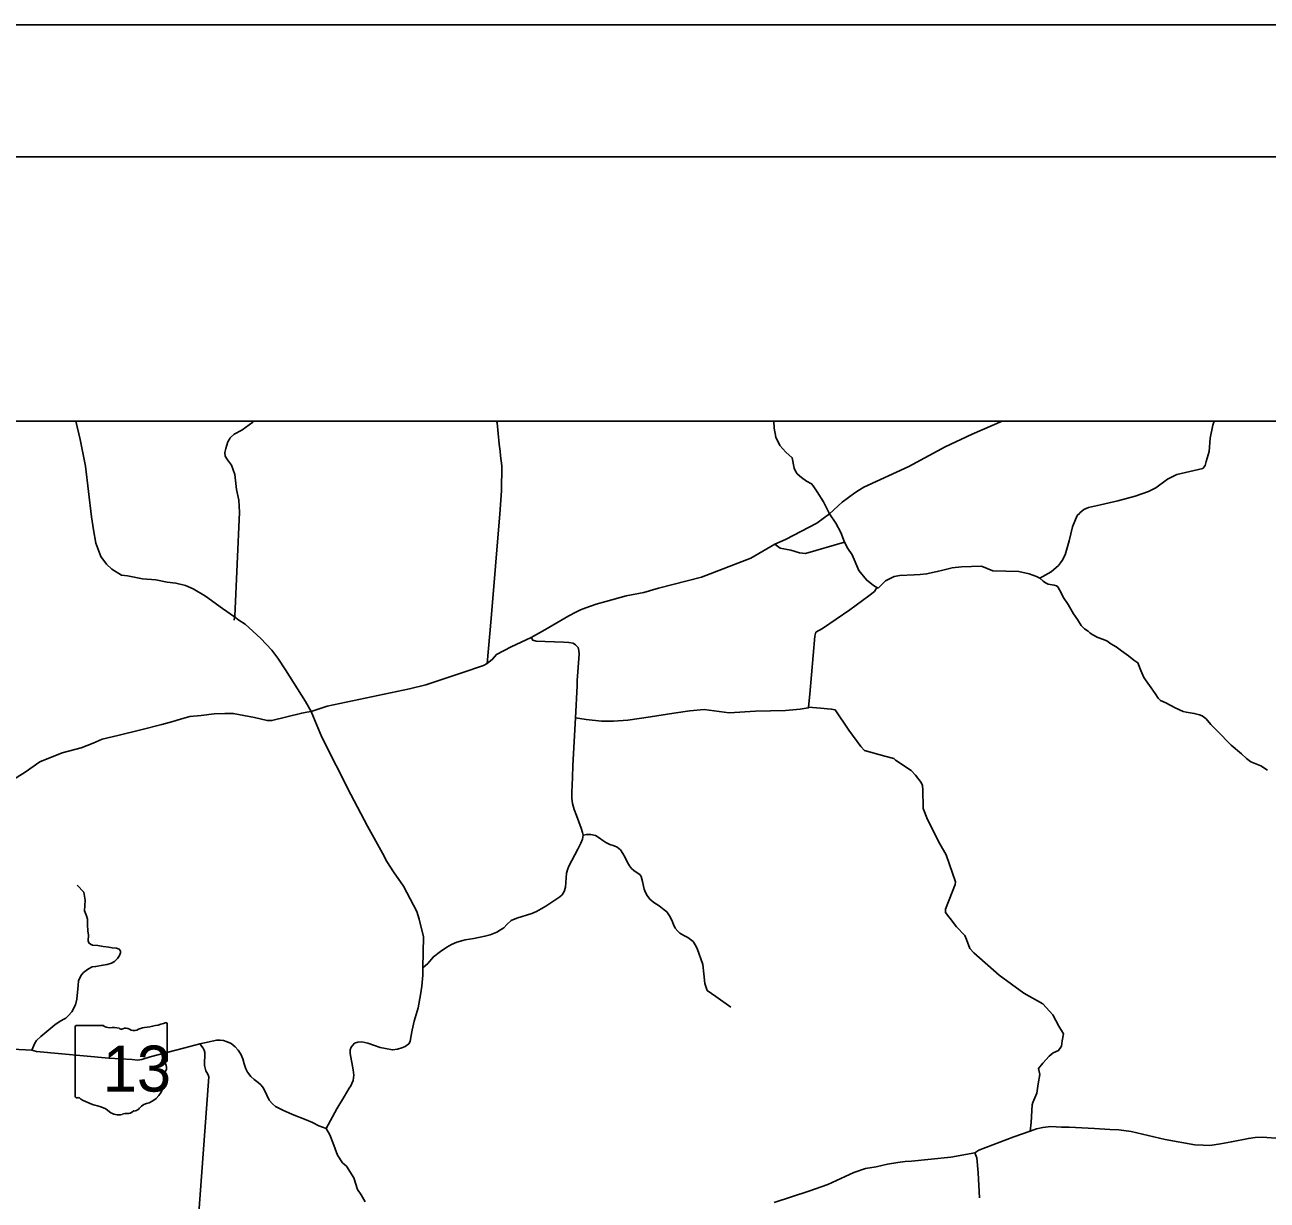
# Model space of a CAD drawing. Extents: x 2025369 to 2161369, y 549489 to 637489.
# Drawn here: x 2056140 to 2074950, y 619698 to 637489 of the extents above; entities that cross this region are included whole.
import ezdxf

# ---------------------------------------------------------------- set-up
doc = ezdxf.new("R2010")
doc.units = 0
for name, color, linetype in [('GM_X_County_Road', 7, 'Continuous'), ('GM_X_State_Route', 7, 'Continuous'), ('GM_X_State_Shield', 7, 'Continuous'), ('GM_X_Township_Road', 7, 'Continuous'), ('SH_Border', 7, 'Continuous'), ('SH_Cut_Line', 7, 'Continuous'), ('SH_Text', 7, 'Continuous')]:
    doc.layers.add(name, color=color, linetype=linetype)

msp = doc.modelspace()

# ---------------------------------------------------------------- linework, layer by layer
at = {"layer": 'GM_X_County_Road'}
for points in [[(2060474, 627097), (2060388, 627244), (2060085, 627725), (2059968, 627901), (2059882, 628022), (2059715, 628201), (2059590, 628313), (2059475, 628416), (2059381, 628478), (2059316, 628529), (2059135, 628654), (2058875, 628843), (2058686, 628953), (2058570, 629004), (2058427, 629039), (2058297, 629053), (2058123, 629087), (2057922, 629105), (2057692, 629151), (2057603, 629159), (2057457, 629250), (2057374, 629323), (2057292, 629442), (2057217, 629642), (2057181, 629846), (2057148, 630040), (2057058, 630808), (2056976, 631214), (2056910, 631489)], [(2068778, 630450), (2068845, 630491), (2069524, 630805), (2070075, 631103), (2070481, 631295), (2070939, 631489)], [(2072114, 630099), (2072116, 630101), (2072172, 630152), (2072243, 630184), (2072429, 630225), (2072690, 630285), (2072950, 630355), (2073152, 630423), (2073266, 630480), (2073439, 630612), (2073584, 630685), (2073976, 630774), (2074009, 630817), (2074026, 630881), (2074073, 631030), (2074087, 631235), (2074127, 631430), (2074150, 631489)], [(2055926, 626042), (2056143, 626179), (2056367, 626333), (2056707, 626468), (2056991, 626543), (2057173, 626618), (2057309, 626676), (2057547, 626731), (2057896, 626816), (2058216, 626899), (2058382, 626944), (2058496, 626978), (2058640, 627017), (2058812, 627035), (2059006, 627058), (2059166, 627065), (2059233, 627065), (2059295, 627065), (2059617, 627004), (2059808, 626957), (2059882, 626957), (2060332, 627070), (2060411, 627087), (2060474, 627097), (2060718, 627178), (2061962, 627440), (2062213, 627498), (2062758, 627679), (2063085, 627790), (2063138, 627821), (2063221, 627887), (2063279, 627959), (2063505, 628074), (2063806, 628217), (2064013, 628331), (2064375, 628541), (2064492, 628605), (2064555, 628635), (2064634, 628666), (2064791, 628718), (2064938, 628762), (2065245, 628845), (2065511, 628898), (2065733, 628960), (2066385, 629131), (2067131, 629415), (2067496, 629629), (2067656, 629701), (2068130, 629945), (2068322, 630088), (2068516, 630263), (2068708, 630407), (2068778, 630450)], [(2068322, 630088), (2068417, 629946), (2068496, 629803), (2068549, 629659), (2068602, 629562), (2068666, 629467), (2068767, 629231), (2068883, 629088), (2068992, 629002), (2069042, 628974), (2069062, 628963), (2069173, 629072), (2069300, 629138), (2069386, 629156), (2069603, 629162), (2069696, 629170)], [(2069696, 629170), (2069794, 629178), (2069955, 629213), (2070039, 629234), (2070179, 629268), (2070320, 629285), (2070623, 629296), (2070794, 629223), (2071189, 629212), (2071345, 629179), (2071459, 629137), (2071510, 629113), (2071679, 629210), (2071790, 629304), (2071821, 629344), (2071848, 629380), (2071893, 629465), (2071952, 629681), (2072005, 629889), (2072075, 630060), (2072114, 630099)], [(2067496, 629629), (2067575, 629569), (2067738, 629537), (2067867, 629498), (2067962, 629486), (2068549, 629659)], [(2064501, 627486), (2064505, 627564), (2064532, 627962), (2064526, 628019), (2064517, 628063), (2064479, 628105), (2064442, 628128), (2064376, 628139), (2064297, 628143), (2063883, 628162), (2063832, 628173), (2063806, 628217)], [(2064430, 626096), (2064439, 626277), (2064478, 626998), (2064501, 627486)], [(2062770, 623629), (2062806, 623639), (2062940, 623659), (2063107, 623692), (2063185, 623714), (2063288, 623754), (2063344, 623788), (2063393, 623818), (2063436, 623873), (2063505, 623933), (2063590, 623968), (2063814, 624035), (2063888, 624067), (2064030, 624150), (2064240, 624287), (2064276, 624321), (2064307, 624370), (2064325, 624437), (2064335, 624579), (2064342, 624650), (2064360, 624713), (2064378, 624754), (2064513, 625012), (2064560, 625103), (2064584, 625164), (2064596, 625221), (2064585, 625262), (2064562, 625331), (2064492, 625523), (2064459, 625609), (2064431, 625704), (2064422, 625779), (2064420, 625876), (2064430, 626096)], [(2057586, 623467), (2057585, 623476), (2057569, 623499), (2057529, 623511), (2057464, 623515), (2057410, 623528), (2057326, 623540), (2057247, 623551), (2057163, 623559), (2057134, 623572), (2057109, 623593), (2057100, 623624), (2057102, 623710), (2057092, 623777), (2057090, 623865), (2057088, 623950), (2057075, 624003), (2057042, 624078), (2057054, 624237), (2057033, 624360), (2056933, 624467)], [(2061092, 621465), (2061111, 621508), (2061120, 621588), (2061113, 621672), (2061065, 621916), (2061067, 621975), (2061082, 622015), (2061133, 622073), (2061182, 622090), (2061242, 622093), (2061332, 622073), (2061432, 622037), (2061521, 622011), (2061602, 621991), (2061705, 621972), (2061780, 621983), (2061849, 622004), (2061900, 622023), (2061953, 622064), (2061972, 622100), (2061986, 622166), (2062005, 622270), (2062036, 622408), (2062096, 622610), (2062133, 622807), (2062149, 622936), (2062166, 623102), (2062166, 623216), (2062240, 623279), (2062325, 623382), (2062435, 623464), (2062530, 623525), (2062599, 623567), (2062680, 623603), (2062770, 623629)], [(2056247, 621966), (2056292, 622076), (2056317, 622115), (2056381, 622175), (2056474, 622252), (2056594, 622353), (2056659, 622395), (2056720, 622430), (2056758, 622452), (2056801, 622494), (2056851, 622550), (2056907, 622655), (2056929, 622738), (2056946, 622949), (2056953, 623016), (2056970, 623062), (2056996, 623107), (2057030, 623146), (2057066, 623172), (2057102, 623198), (2057161, 623229), (2057211, 623233), (2057324, 623256), (2057385, 623266), (2057451, 623287), (2057495, 623310), (2057543, 623356), (2057575, 623402), (2057589, 623444), (2057586, 623467)], [(2060702, 620782), (2060862, 621078), (2060979, 621274), (2061053, 621392), (2061076, 621429), (2061092, 621465)]]:
    msp.add_lwpolyline(points, dxfattribs=at)
at = {"layer": 'GM_X_State_Route'}
for points in [[(2056317, 621949), (2056247, 621966), (2055166, 622026), (2054991, 622055), (2054759, 622107), (2054579, 622183), (2054430, 622277), (2054349, 622347), (2054250, 622451), (2054118, 622661), (2053956, 622954), (2053866, 623163), (2053790, 623366), (2053768, 623410), (2053723, 623428), (2053665, 623433)], [(2058791, 622063), (2058560, 622006), (2058036, 621868), (2057910, 621827), (2057853, 621819), (2057764, 621828), (2057411, 621849), (2056317, 621949)], [(2061292, 619671), (2061234, 619780), (2061179, 619860), (2061121, 620035), (2061008, 620210), (2060950, 620265), (2060873, 620381), (2060804, 620572), (2060759, 620687), (2060702, 620782), (2060645, 620802), (2060591, 620821), (2060497, 620873), (2060398, 620914), (2060191, 620992), (2060045, 621060), (2059934, 621114), (2059892, 621154), (2059839, 621209), (2059806, 621285), (2059760, 621384), (2059739, 621415), (2059714, 621442), (2059671, 621481), (2059613, 621524), (2059564, 621568), (2059513, 621633), (2059485, 621687), (2059460, 621760), (2059438, 621837), (2059410, 621909), (2059372, 621970), (2059325, 622018), (2059263, 622069), (2059203, 622095), (2059146, 622114), (2059096, 622121), (2059045, 622120), (2058791, 622063)], [(2075146, 620629), (2074879, 620652), (2074769, 620646), (2074667, 620632), (2074409, 620582), (2074243, 620548), (2074083, 620526), (2073980, 620531), (2073855, 620536), (2073407, 620616), (2072893, 620736), (2072705, 620761), (2072568, 620769), (2072337, 620784), (2071950, 620801), (2071836, 620802), (2071676, 620811), (2071553, 620796), (2071457, 620777), (2071363, 620742), (2071113, 620655), (2070585, 620454), (2070522, 620414), (2070163, 620351), (2069567, 620287), (2069470, 620284), (2069360, 620270), (2069203, 620241), (2069028, 620204), (2068870, 620175), (2068690, 620115), (2068297, 619937), (2068012, 619834), (2067487, 619663)]]:
    msp.add_lwpolyline(points, dxfattribs=at)
at = {"layer": 'GM_X_State_Shield'}
for p, q in [((2056904, 622323), (2056904, 621266)), ((2057325, 622341), (2056918, 622341)), ((2058296, 621814), (2058296, 622367)), ((2058296, 621814), (2058296, 621814))]:
    msp.add_line(p, q, dxfattribs=at)
for centre, radius, start, end in [((2056920, 622325), 16.1, 98.1301, 188.1301), ((2057422, 622464), 156, 231.6195, 271.1119), ((2057474, 621748), 562, 80.4867, 94.9883), ((2057602, 622330), 45.1, 219.7921, 297.1024), ((2057668, 622208), 93.8, 54.4667, 119.1411), ((2057789, 622376), 113, 233.8562, 294.8282), ((2057988, 622018), 297, 97.3462, 120.7689), ((2057800, 623781), 1476, 275.8445, 288.9065), ((2058281, 622369), 15.5, 351.8621, 97.738), ((2058292, 621774), 24, 107.944, 210.337), ((2058140, 621704), 144, 340.033, 23.6496), ((2058279, 621812), 16.6, 289.6038, 7.7341), ((2057883, 621513), 369, 292.3089, 8.9858), ((2058352, 621583), 105, 136.8065, 186.9296), ((2056920, 621264), 16.3, 171.9584, 258.3066), ((2056922, 621372), 124, 267.339, 280.6039), ((2056948, 621205), 44.8, 29.7484, 93.2717), ((2057513, 622154), 1066, 240.4129, 257.1985), ((2057195, 620791), 334, 47.1842, 75.836), ((2058038, 620969), 202, 94.4031, 142.5768), ((2057556, 621200), 212, 230.7004, 286.2918), ((2057678, 620835), 174, 85.6951, 111.2099), ((2057694, 621121), 113, 268.777, 315.5493), ((2057796, 621018), 31.8, 65.7517, 132.6484), ((2057782, 621164), 119, 282.8732, 323.2771)]:
    msp.add_arc(centre, radius, start, end, dxfattribs=at)
at = {"layer": 'GM_X_Township_Road'}
for points in [[(2059237, 631216), (2059250, 631240), (2059309, 631291), (2059427, 631355), (2059593, 631473), (2059609, 631489)], [(2063344, 630963), (2063335, 631035), (2063321, 631143), (2063292, 631466), (2063282, 631489)], [(2067759, 630934), (2067759, 630937), (2067664, 631023), (2067569, 631123), (2067511, 631247), (2067484, 631384), (2067483, 631489)], [(2059311, 628477), (2059316, 628529), (2059317, 628536), (2059392, 630114), (2059380, 630294), (2059347, 630456), (2059319, 630684), (2059268, 630822), (2059208, 630904), (2059173, 630960), (2059167, 631014), (2059182, 631078), (2059215, 631175), (2059237, 631216)], [(2063138, 627821), (2063201, 628502), (2063330, 630086), (2063355, 630437), (2063363, 630812), (2063344, 630963)], [(2068322, 630088), (2068233, 630267), (2068139, 630419), (2068077, 630512), (2068051, 630542), (2067974, 630584), (2067897, 630635), (2067833, 630693), (2067807, 630732), (2067787, 630777), (2067759, 630934)], [(2074953, 626208), (2074852, 626274), (2074705, 626335), (2074637, 626385), (2074560, 626456), (2074406, 626583), (2074192, 626801), (2074098, 626899), (2074025, 626985), (2073967, 627031), (2073928, 627045), (2073846, 627067), (2073725, 627084), (2073676, 627095), (2073558, 627151), (2073415, 627228), (2073333, 627263), (2073299, 627295), (2073256, 627367), (2073082, 627608), (2073036, 627718), (2072992, 627833), (2072932, 627874), (2072851, 627940), (2072747, 628015), (2072666, 628072), (2072585, 628119), (2072523, 628164), (2072459, 628192), (2072386, 628216), (2072302, 628260), (2072266, 628284), (2072239, 628310), (2072182, 628347), (2072132, 628397), (2072078, 628487), (2072019, 628575), (2071938, 628713), (2071859, 628827), (2071832, 628892), (2071783, 628982), (2071759, 628998), (2071726, 629006), (2071636, 629023), (2071593, 629045), (2071559, 629066), (2071510, 629113)], [(2064478, 626998), (2064640, 626973), (2064871, 626948), (2065052, 626948), (2065272, 626965), (2065611, 627015), (2065968, 627071), (2066210, 627104), (2066424, 627126), (2066804, 627076), (2067201, 627100), (2067656, 627108), (2067878, 627130), (2068002, 627149), (2068003, 627161), (2068025, 627357), (2068100, 628236), (2068118, 628294), (2068219, 628350), (2068633, 628635), (2068921, 628846), (2069006, 628912), (2069042, 628974)], [(2069732, 625965), (2069731, 625977), (2069709, 626022), (2069625, 626132), (2069562, 626203), (2069325, 626358), (2069295, 626382), (2069161, 626418), (2068854, 626505), (2068800, 626566), (2068616, 626813), (2068411, 627120), (2068351, 627132), (2068188, 627143), (2068003, 627161)], [(2062166, 623216), (2062174, 623682), (2062109, 623949), (2062075, 624069), (2061875, 624453), (2061722, 624667), (2061619, 624824), (2061553, 624948), (2061329, 625358), (2061078, 625841), (2060638, 626704), (2060512, 627009), (2060474, 627097)], [(2071363, 620742), (2071376, 620874), (2071393, 621141), (2071403, 621174), (2071465, 621315), (2071481, 621458), (2071508, 621602), (2071486, 621693), (2071555, 621774), (2071647, 621876), (2071709, 621930), (2071791, 621964), (2071835, 622030), (2071845, 622108), (2071866, 622216), (2071795, 622332), (2071706, 622503), (2071552, 622669), (2071265, 622833), (2070893, 623106), (2070511, 623444), (2070449, 623506), (2070398, 623645), (2070370, 623703), (2070245, 623837), (2070148, 623962), (2070132, 623986), (2070080, 624050), (2070082, 624104), (2070183, 624360), (2070224, 624476), (2070232, 624514), (2070090, 624925), (2069992, 625090), (2069805, 625461), (2069744, 625626), (2069739, 625920), (2069732, 625965)], [(2064596, 625221), (2064648, 625235), (2064712, 625232), (2064782, 625218), (2064836, 625181), (2064889, 625142), (2064936, 625111), (2064995, 625084), (2065063, 625061), (2065109, 625039), (2065158, 625000), (2065194, 624947), (2065228, 624885), (2065264, 624811), (2065293, 624758), (2065324, 624719), (2065362, 624687), (2065413, 624655), (2065454, 624626), (2065473, 624599), (2065490, 624523), (2065518, 624407), (2065538, 624356), (2065561, 624309), (2065604, 624255), (2065664, 624205), (2065745, 624153), (2065822, 624094), (2065862, 624061), (2065903, 624001), (2065936, 623935), (2065961, 623870), (2065989, 623813), (2066026, 623771), (2066057, 623737), (2066118, 623704), (2066177, 623672), (2066221, 623642), (2066257, 623612), (2066291, 623561), (2066318, 623505), (2066405, 623266), (2066423, 623125), (2066434, 622977), (2066470, 622873), (2066603, 622779), (2066827, 622620)], [(2058575, 616832), (2058927, 621567), (2058910, 621606), (2058882, 621657), (2058859, 621736), (2058863, 621933), (2058857, 621970), (2058842, 621999), (2058791, 622063)], [(2070596, 619732), (2070572, 620109), (2070553, 620340), (2070522, 620414)]]:
    msp.add_lwpolyline(points, dxfattribs=at)
at = {"layer": 'SH_Border'}
msp.add_lwpolyline([(2033369, 635489), (2159369, 635489), (2159369, 551489), (2033369, 551489)], close=True, dxfattribs=at)
at = {"layer": 'SH_Cut_Line'}
msp.add_lwpolyline([(2025369, 549489), (2161369, 549489), (2161369, 637489), (2025369, 637489)], close=True, dxfattribs=at)
at = {"layer": 'SH_Text'}
msp.add_line((2092420, 631489), (2037369, 631489), dxfattribs=at)

# ---------------------------------------------------------------- texts
at = {"layer": 'GM_X_State_Shield'}
msp.add_text('13', height=696.1, dxfattribs=at).set_placement((2057318, 621341))

doc.saveas('drawing.dxf')
